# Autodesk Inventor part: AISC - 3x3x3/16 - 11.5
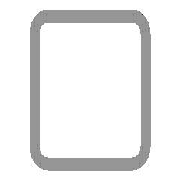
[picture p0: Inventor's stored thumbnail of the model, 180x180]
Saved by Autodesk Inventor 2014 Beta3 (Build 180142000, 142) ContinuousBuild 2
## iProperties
IsCustomPart: 1
Created: 2010-11
Part Number: AISC - 3x3x3/16 - 11.5
Material: Steel, Mild
Description: Tube
Document SubType Name: Modeling
Standard: ANSI
Designer: Beta-8540w
Standards Organization: ANSI
Language: en-US
Size Designation: 3x3x3/16
Categories: <MemberInstance><Categories><Category DisplayName="Structural Shapes" InternalName="089c4875-fa83-4c05-b084-43b9cc11f5ed" Mnemonic="GRDR"><CategoryParameter Dis
Stock Number: 3x3x3/16
Density: 7.86 g/cm^3
Appearance: Steel
_CCFamilyMember: 9
_CCFamilyDisplayName: ANSI AISC (Square) - Tube
_FrameMemberDoc: Frame Member File
_Version: 15.0.0
_GetPNFromCC: 1
G_L: 11.500 in
G_W: 3.000 in
G_H: 3.000 in
Author: Beta-8540w
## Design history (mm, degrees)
node "Start plane"
node "End plane"
sketch "Sketch"
  geometry: L1 (-38.1, -28.575)-(-38.1, 28.575); L2 (-28.575, 38.1)-(28.575, 38.1); L3 (38.1, 28.575)-(38.1, -28.575); L4 (28.575, -38.1)-(-28.575, -38.1); L5 (-28.575, 33.337)-(28.575, 33.338); L6 (33.338, 28.575)-(33.338, -28.575); L7 (28.575, -33.337)-(-28.575, -33.338); L8 (-33.338, -28.575)-(-33.338, 28.575); L9 (0, 56.102)-(0, -56.102) reference; L10 (-56.102, 0)-(56.102, 0) reference; A1 r 9.525 centre (-28.575, -28.575) between (-38.1, -28.575) and (-28.575, -38.1); A2 r 9.525 centre (-28.575, 28.575) between (-28.575, 38.1) and (-38.1, 28.575); A3 r 9.525 centre (28.575, 28.575) between (38.1, 28.575) and (28.575, 38.1); A4 r 9.525 centre (28.575, -28.575) between (28.575, -38.1) and (38.1, -28.575); A5 r 4.763 centre (-28.575, 28.575) between (-28.575, 33.337) and (-33.338, 28.575); A6 r 4.763 centre (28.575, 28.575) between (33.338, 28.575) and (28.575, 33.338); A7 r 4.763 centre (28.575, -28.575) between (28.575, -33.337) and (33.338, -28.575); A8 r 4.763 centre (-28.575, -28.575) between (-33.338, -28.575) and (-28.575, -33.338)
  constraints: 16 end point, 16 point on circle, 8 centre point, 8 tangent, 4 parallel, 3 equal radius, 2 perpendicular, 7 other
  dimensions: "d10" = 76.2 distance between parallel lines of L2 L4 (= G_H); "d11" = 76.2 distance between parallel lines of L1 L3 (= G_W); "d12" = 4.7625 distance between parallel lines of L3 L6 (= G_T); "d15" = 38.1 distance between parallel lines of L2 L10 (= 0.5 x d10); "d16" = 38.1 distance between parallel lines of L9 L3 (= 0.5 x d11); "d17" = 9.525 radius of A1 (= G_IR)
extrude "Body" new body sketch "Sketch" stored distance "d3" = 292.1 (= G_L); taper "d4" = 0 deg
node "Driven Length"
  sketch "Sketch3"
    geometry: L1 (0, 0)-(10, 0) reference
    constraints: 2 end point, 1 horizontal
  workplane "Work Plane3"
  sketch "Sketch4"
    geometry: L1 (-2, 0)-(12, 0) reference; L2 (-2, 292.1)-(12, 292.1) reference
    dimensions: "d19" = 292.1 distance between parallel lines of L1 L2 (derived)
workplane "Work Plane4"
split "Split1"
body "Solid1"
other parameters: "G_W" = 76.2 [user parameter; used in 1 equation term], "G_H" = 76.2 [user parameter; used in 1 equation term], "G_T" = 4.7625 [user parameter; used in 1 equation term], "G_IR" = 9.525 [user parameter; used in 1 equation term], "G_L" = 292.1 (= d19) [user parameter; used in 1 equation term], "G_OFFSET_START" = 0 [user parameter; used in 1 equation term], "G_OFFSET_END" = 38.1 [user parameter; used in 1 equation term], "d13" = 0 (computed from G_OFFSET_START), "d14" = 292.1 (= G_OFFSET_END + B_L), "B_L" = 254 [user parameter; used in 1 equation term], "d18" = 90 deg
